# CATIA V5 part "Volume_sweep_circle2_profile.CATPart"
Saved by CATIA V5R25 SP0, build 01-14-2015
Part number: Part1
Bounding box of the stored display mesh (mm): x -183.601 to 0, y -55 to 90.736, z -54.999 to 55
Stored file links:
  E:\cadcim\GSD_cat_v5-6r2014\Part_files\Volume_sweep_circle2_profile.CATPart
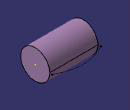
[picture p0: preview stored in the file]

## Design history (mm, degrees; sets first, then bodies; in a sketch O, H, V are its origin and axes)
Set1
  Sketch1 on xy-plane, origin (0, 0, 0), H (1, 0, 0), V (0, 1, 0)
    line L1 (0, 0) -> (-183.1008, 0)
    horizontal: L1 H
  Sketch2 on xy-plane, origin (0, 0, 0), H (1, 0, 0), V (0, 1, 0)
    spline S1 through (0, 65.5148) (-89.6654, 90.7245) (-183.6013, 65.5148)
    point P1 (0, 65.5148)
    coincidence: P1 V
  Sweep1: type Circle, Guide Sketch1, Reference Sketch2, Radius 55
Body1 (main body)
